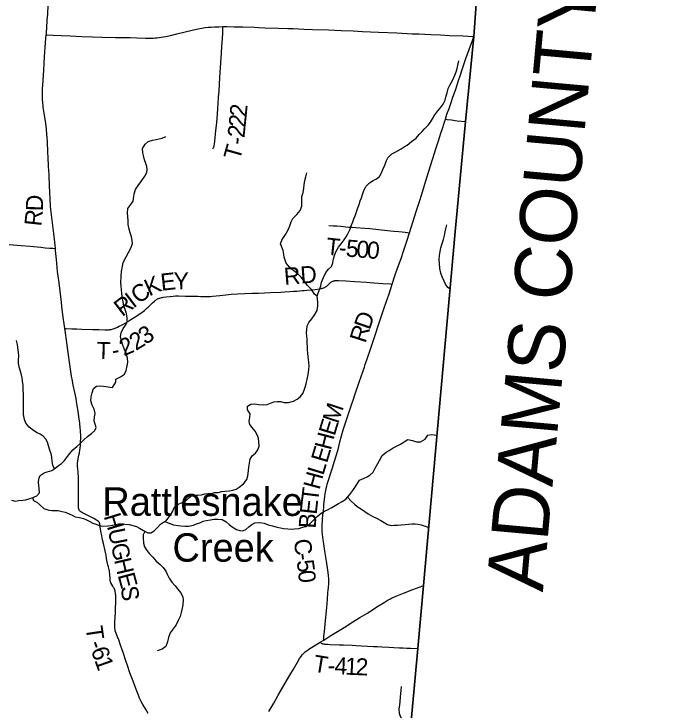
# Model space of a CAD drawing. Extents: x 1451455 to 1749751, y 218250 to 574981.
# Drawn here: x 1622321 to 1633736, y 302693 to 314948 of the extents above; entities that cross this region are included whole.
import ezdxf

# ---------------------------------------------------------------- set-up
doc = ezdxf.new("R2010")
doc.units = 0
for name, color, linetype in [('GM_X_Adjacent_County', 7, 'Continuous'), ('GM_X_Adjacent_County_Text', 7, 'Continuous'), ('GM_X_County', 7, 'Continuous'), ('GM_X_County_Road', 7, 'Continuous'), ('GM_X_County_Road_Text', 7, 'Continuous'), ('GM_X_Minor_River', 7, 'Continuous'), ('GM_X_Minor_River_Text', 7, 'Continuous'), ('GM_X_Township', 7, 'Continuous'), ('GM_X_Township_Road', 7, 'Continuous'), ('GM_X_Township_Road_Text', 7, 'Continuous')]:
    doc.layers.add(name, color=color, linetype=linetype)

msp = doc.modelspace()

# ---------------------------------------------------------------- linework, layer by layer
at = {"layer": 'GM_X_Adjacent_County'}
msp.add_lwpolyline([(1628937, 298348), (1629433, 303775), (1629536, 304887), (1630089, 311112), (1630271, 313053), (1630419, 314553), (1630488, 315536), (1630722, 318179), (1630769, 318617), (1630954, 320913), (1631260, 324446), (1631493, 327825), (1631870, 332224), (1631939, 332801), (1632333, 337652), (1632719, 342502), (1633085, 347092), (1633093, 347197), (1633154, 348076), (1633224, 348842), (1633265, 349678), (1633736, 355308)], dxfattribs=at)
at = {"layer": 'GM_X_County'}
msp.add_lwpolyline([(1628937, 298348), (1629433, 303775), (1629536, 304887), (1630089, 311112), (1630271, 313053), (1630419, 314553), (1630488, 315536), (1630722, 318179), (1630769, 318617), (1630954, 320913), (1631260, 324446), (1631493, 327825), (1631870, 332224), (1631939, 332801), (1632333, 337652), (1632719, 342502), (1633085, 347092), (1633093, 347197), (1633154, 348076), (1633224, 348842), (1633265, 349678), (1633736, 355308)], dxfattribs=at)
at = {"layer": 'GM_X_County_Road'}
for points in [[(1622888, 314578), (1623011, 314574), (1623150, 314568), (1623309, 314560), (1623517, 314553), (1623706, 314547), (1623876, 314542), (1624109, 314536), (1624270, 314533), (1624368, 314531), (1624483, 314528), (1624637, 314523), (1624685, 314522), (1624729, 314522), (1624778, 314523), (1624808, 314525), (1624841, 314528), (1624877, 314532), (1624912, 314538), (1624997, 314553), (1625077, 314569), (1625189, 314595), (1625316, 314627), (1625482, 314669), (1625565, 314687), (1625628, 314699), (1625687, 314707), (1625743, 314713), (1625795, 314716), (1625851, 314719), (1625890, 314722), (1625932, 314723), (1625999, 314724)], [(1625999, 314724), (1626069, 314724), (1626198, 314723), (1626355, 314719), (1626555, 314713), (1626627, 314710), (1626739, 314705), (1626975, 314698), (1627142, 314693), (1627240, 314690), (1627424, 314682), (1627581, 314676), (1627863, 314667), (1628083, 314659), (1628296, 314649), (1628460, 314641), (1628742, 314628), (1629066, 314613), (1629335, 314600), (1629453, 314595), (1629663, 314586), (1629833, 314578), (1629990, 314571), (1630233, 314562), (1630318, 314558), (1630419, 314553)], [(1623051, 310821), (1623047, 310875), (1623041, 310930), (1623021, 311084), (1623004, 311224), (1622992, 311319), (1622980, 311410), (1622969, 311504), (1622964, 311566), (1622957, 311700), (1622953, 311805), (1622948, 311926), (1622946, 311979), (1622943, 312048), (1622939, 312120), (1622932, 312264), (1622924, 312434), (1622920, 312504), (1622917, 312569), (1622914, 312645), (1622911, 312709), (1622908, 312765), (1622903, 312831), (1622895, 312919), (1622883, 313017), (1622872, 313095), (1622844, 313270), (1622838, 313305), (1622834, 313338), (1622829, 313383), (1622826, 313448), (1622825, 313509), (1622825, 313566), (1622826, 313635), (1622829, 313694), (1622845, 313956), (1622853, 314073), (1622862, 314198), (1622872, 314362), (1622883, 314515), (1622888, 314578)], [(1629919, 313096), (1629947, 313181), (1629985, 313285), (1630022, 313391), (1630053, 313481), (1630080, 313561), (1630101, 313624), (1630152, 313776), (1630179, 313860), (1630228, 314007), (1630282, 314162), (1630396, 314479), (1630402, 314500), (1630419, 314553)], [(1629289, 311095), (1629317, 311188), (1629412, 311485), (1629463, 311648), (1629503, 311773), (1629572, 311992), (1629693, 312383), (1629759, 312593), (1629803, 312734), (1629834, 312831), (1629868, 312934), (1629897, 313028), (1629919, 313096)], [(1628984, 310192), (1629031, 310336), (1629072, 310457), (1629146, 310661), (1629178, 310754), (1629243, 310947), (1629289, 311095)], [(1622237, 310892), (1622449, 310873), (1622609, 310858), (1622793, 310841), (1622871, 310833), (1622949, 310826), (1622980, 310823), (1623006, 310822), (1623051, 310821)], [(1627776, 303926), (1627781, 303991), (1627789, 304079), (1627800, 304206), (1627817, 304389), (1627829, 304497), (1627836, 304572), (1627842, 304637), (1627852, 304758), (1627860, 304849), (1627865, 304921), (1627866, 304950), (1627866, 304977), (1627865, 304997), (1627864, 305019), (1627862, 305044), (1627860, 305068), (1627849, 305155), (1627825, 305314), (1627799, 305488), (1627780, 305618), (1627769, 305692), (1627757, 305783), (1627751, 305842), (1627749, 305863), (1627748, 305885), (1627747, 305907), (1627748, 305931), (1627749, 305952), (1627750, 305974), (1627753, 306015), (1627757, 306055), (1627763, 306127), (1627771, 306205), (1627776, 306264), (1627781, 306310), (1627798, 306449), (1627805, 306505), (1627809, 306532), (1627815, 306559), (1627822, 306597), (1627830, 306633), (1627840, 306671), (1627876, 306793), (1627901, 306872), (1627923, 306940), (1627969, 307077), (1627992, 307149), (1628029, 307281), (1628063, 307415), (1628090, 307520), (1628120, 307624), (1628166, 307765), (1628214, 307911), (1628271, 308082), (1628301, 308169), (1628326, 308244), (1628409, 308482), (1628495, 308730), (1628509, 308774), (1628548, 308892), (1628594, 309029), (1628681, 309294), (1628741, 309475), (1628842, 309773), (1628928, 310021), (1628984, 310192)], [(1627776, 303926), (1627904, 304005), (1628135, 304148), (1628288, 304245), (1628414, 304322), (1628534, 304396), (1628742, 304527), (1628839, 304588), (1628909, 304631), (1628941, 304648), (1628961, 304658), (1628983, 304668), (1629022, 304685), (1629065, 304703), (1629180, 304749), (1629348, 304815), (1629474, 304863), (1629536, 304887)], [(1626809, 302667), (1626897, 302817), (1626977, 302956), (1627018, 303027), (1627080, 303135), (1627182, 303308), (1627242, 303413), (1627315, 303537), (1627353, 303599), (1627377, 303635), (1627399, 303664), (1627411, 303678), (1627423, 303691), (1627437, 303704), (1627452, 303718), (1627467, 303730), (1627484, 303742), (1627533, 303776), (1627591, 303812), (1627713, 303887)], [(1627713, 303887), (1627776, 303926)]]:
    msp.add_lwpolyline(points, dxfattribs=at)
at = {"layer": 'GM_X_Minor_River'}
for points in [[(1628037, 310840), (1628082, 310903), (1628135, 310969), (1628172, 311022), (1628202, 311074), (1628235, 311150), (1628262, 311216), (1628289, 311289), (1628309, 311341), (1628330, 311395), (1628355, 311465), (1628377, 311533), (1628400, 311595), (1628421, 311655), (1628440, 311712), (1628458, 311768), (1628483, 311838), (1628522, 311916), (1628585, 311973), (1628647, 312013), (1628708, 312046), (1628762, 312085), (1628793, 312151), (1628815, 312207), (1628852, 312285), (1628883, 312365), (1628906, 312416), (1628979, 312484), (1629045, 312523), (1629140, 312576), (1629196, 312607), (1629247, 312639), (1629325, 312704), (1629404, 312763), (1629459, 312825), (1629508, 312876), (1629552, 312928), (1629619, 312989), (1629655, 313041), (1629692, 313103), (1629735, 313172), (1629786, 313240), (1629828, 313292), (1629883, 313359), (1629914, 313429), (1629933, 313505), (1629948, 313559), (1629970, 313638), (1629995, 313696), (1630044, 313776), (1630087, 313868), (1630110, 313929), (1630127, 313987), (1630142, 314071), (1630154, 314123)], [(1624231, 310505), (1624245, 310575), (1624299, 310674), (1624341, 310748), (1624382, 310824), (1624407, 310905), (1624404, 310957), (1624393, 311026), (1624367, 311094), (1624350, 311158), (1624333, 311239), (1624330, 311311), (1624326, 311375), (1624319, 311439), (1624328, 311521), (1624377, 311593), (1624420, 311654), (1624435, 311732), (1624439, 311784), (1624460, 311856), (1624507, 311928), (1624576, 312015), (1624627, 312095), (1624662, 312158), (1624666, 312212), (1624659, 312265), (1624645, 312315), (1624620, 312379), (1624603, 312454), (1624591, 312504), (1624588, 312578), (1624631, 312656), (1624688, 312703), (1624760, 312728), (1624824, 312740), (1624876, 312749), (1624929, 312760), (1624995, 312788)], [(1627659, 309980), (1627612, 310013), (1627565, 310090), (1627487, 310175), (1627434, 310249), (1627379, 310316), (1627318, 310373), (1627250, 310428), (1627177, 310492), (1627117, 310559), (1627083, 310664), (1627077, 310716), (1627062, 310782), (1627039, 310841), (1627017, 310901), (1627038, 310963), (1627067, 311014), (1627103, 311068), (1627152, 311146), (1627181, 311218), (1627204, 311289), (1627232, 311345), (1627305, 311416), (1627362, 311486), (1627391, 311566), (1627394, 311630), (1627392, 311680), (1627391, 311736), (1627414, 311804), (1627429, 311882), (1627433, 311942), (1627442, 312018), (1627461, 312080), (1627482, 312150)], [(1630001, 310104), (1629965, 310131), (1629924, 310192), (1629896, 310244), (1629861, 310319), (1629840, 310387), (1629823, 310465), (1629816, 310554), (1629812, 310626), (1629815, 310696), (1629826, 310764), (1629839, 310832), (1629864, 310904), (1629884, 310977), (1629903, 311047), (1629916, 311111), (1629929, 311163), (1629945, 311237)], [(1624992, 306005), (1625013, 306040), (1625076, 306127), (1625119, 306197), (1625143, 306261), (1625214, 306320), (1625274, 306341), (1625349, 306379), (1625402, 306432), (1625454, 306468), (1625510, 306475), (1625560, 306474), (1625624, 306484), (1625681, 306501), (1625733, 306505), (1625797, 306508), (1625851, 306521), (1625921, 306523), (1625979, 306542), (1626033, 306549), (1626115, 306551), (1626176, 306562), (1626232, 306581), (1626290, 306619), (1626365, 306674), (1626422, 306755), (1626441, 306815), (1626452, 306903), (1626458, 306969), (1626467, 307041), (1626480, 307111), (1626515, 307167), (1626573, 307216), (1626618, 307272), (1626639, 307338), (1626636, 307414), (1626626, 307474), (1626609, 307528), (1626572, 307601), (1626518, 307670), (1626477, 307720), (1626466, 307774), (1626478, 307848), (1626479, 307906), (1626436, 307977), (1626433, 308045), (1626493, 308081), (1626565, 308082), (1626631, 308073), (1626715, 308068), (1626781, 308075), (1626839, 308095), (1626898, 308118), (1626956, 308128), (1627018, 308125), (1627082, 308108), (1627156, 308107), (1627244, 308130), (1627311, 308168), (1627363, 308205), (1627408, 308269), (1627433, 308325), (1627451, 308378), (1627468, 308438), (1627487, 308518), (1627497, 308574), (1627508, 308634), (1627515, 308688), (1627519, 308748), (1627516, 308818), (1627505, 308909), (1627496, 308977), (1627491, 309035), (1627489, 309093), (1627486, 309147), (1627485, 309223), (1627479, 309279), (1627476, 309330), (1627477, 309394), (1627487, 309458), (1627514, 309517), (1627565, 309579), (1627620, 309654), (1627659, 309726), (1627673, 309808), (1627674, 309876), (1627665, 309926), (1627659, 309980), (1627686, 310050), (1627707, 310108), (1627725, 310162), (1627740, 310224), (1627773, 310306), (1627816, 310399), (1627863, 310457), (1627916, 310504), (1627940, 310568), (1627951, 310636), (1627968, 310698), (1627990, 310762), (1628037, 310840)], [(1622281, 306386), (1622340, 306373), (1622407, 306381), (1622477, 306386), (1622527, 306393), (1622587, 306413), (1622655, 306438), (1622722, 306465), (1622770, 306519), (1622767, 306593), (1622762, 306647), (1622754, 306701), (1622761, 306763), (1622786, 306821), (1622856, 306868), (1622909, 306888), (1622989, 306913), (1623039, 306943), (1623108, 306996), (1623159, 307033), (1623209, 307087), (1623262, 307156), (1623305, 307208), (1623359, 307274), (1623428, 307333), (1623495, 307392), (1623554, 307448), (1623616, 307507), (1623685, 307560), (1623746, 307614), (1623772, 307666), (1623753, 307726), (1623735, 307778), (1623742, 307856), (1623753, 307912), (1623736, 307988), (1623699, 308061), (1623677, 308137), (1623684, 308209), (1623699, 308277), (1623722, 308355), (1623776, 308397), (1623835, 308400), (1623901, 308397), (1623982, 308384), (1624058, 308371), (1624113, 308463), (1624118, 308517), (1624197, 308562), (1624267, 308608), (1624298, 308673), (1624317, 308755), (1624328, 308819), (1624322, 308887), (1624297, 308974), (1624262, 309054), (1624235, 309135), (1624212, 309215), (1624197, 309267), (1624209, 309337), (1624244, 309411), (1624289, 309477), (1624314, 309530), (1624316, 309596), (1624305, 309677), (1624280, 309745), (1624259, 309803), (1624243, 309878), (1624232, 309938), (1624221, 310026), (1624214, 310098), (1624209, 310156), (1624205, 310219), (1624210, 310323), (1624217, 310413), (1624231, 310505)], [(1623036, 306940), (1623004, 307005), (1622995, 307077), (1622986, 307143), (1622976, 307202), (1622955, 307268), (1622932, 307346), (1622915, 307409), (1622885, 307465), (1622836, 307516), (1622784, 307548), (1622728, 307575), (1622667, 307616), (1622589, 307676), (1622530, 307743), (1622505, 307810), (1622492, 307894), (1622488, 307952), (1622487, 308006), (1622488, 308062), (1622490, 308112), (1622491, 308178), (1622488, 308246), (1622483, 308339), (1622481, 308405), (1622474, 308485), (1622465, 308543), (1622452, 308597), (1622430, 308676), (1622415, 308732), (1622402, 308804), (1622403, 308862), (1622405, 308924), (1622404, 308996), (1622391, 309073), (1622382, 309127), (1622364, 309197)], [(1628805, 307172), (1628877, 307231), (1628928, 307265), (1628998, 307308), (1629059, 307339), (1629127, 307373), (1629196, 307416), (1629256, 307455), (1629342, 307438), (1629410, 307414), (1629480, 307417), (1629563, 307462), (1629613, 307530), (1629674, 307543), (1629766, 307531)], [(1622646, 306434), (1622667, 306384), (1622725, 306355), (1622776, 306309), (1622849, 306240), (1622935, 306213), (1622991, 306206), (1623047, 306207), (1623101, 306205), (1623169, 306190), (1623221, 306176), (1623295, 306149), (1623346, 306124), (1623400, 306097), (1623476, 306085), (1623546, 306068), (1623598, 306043), (1623657, 306013), (1623713, 305986), (1623769, 305963), (1623833, 305937), (1623889, 305930), (1623983, 305939), (1624059, 305950), (1624113, 305960), (1624163, 305969), (1624215, 305972), (1624277, 305968), (1624351, 305959), (1624417, 305944), (1624479, 305923), (1624535, 305897), (1624600, 305854), (1624678, 305811), (1624732, 305815), (1624790, 305850), (1624847, 305909), (1624904, 305967), (1624974, 306010), (1625040, 305989), (1625132, 305956), (1625210, 305940), (1625262, 305935), (1625334, 305928), (1625394, 305932), (1625482, 305947), (1625538, 305974), (1625597, 305991), (1625653, 306017), (1625707, 306028), (1625781, 306045), (1625840, 306051), (1625912, 306056), (1625986, 306047), (1626059, 306006), (1626111, 305960), (1626166, 305921), (1626242, 305874), (1626302, 305852), (1626354, 305847), (1626406, 305870), (1626459, 305920), (1626513, 305959), (1626563, 305989), (1626654, 305998), (1626726, 305983), (1626799, 305956), (1626875, 305935), (1626933, 305921), (1627015, 305904), (1627071, 305889), (1627147, 305882), (1627205, 305878), (1627265, 305881), (1627341, 305892), (1627411, 305912), (1627461, 305927), (1627532, 305970), (1627605, 306042), (1627664, 306101), (1627734, 306158), (1627791, 306192), (1627857, 306225), (1627922, 306262), (1627980, 306296), (1628036, 306327), (1628103, 306363), (1628165, 306408), (1628234, 306487), (1628289, 306561), (1628326, 306612), (1628359, 306666), (1628407, 306740), (1628488, 306775), (1628540, 306798), (1628591, 306828), (1628645, 306881), (1628684, 306949), (1628729, 307031), (1628760, 307084), (1628805, 307172)], [(1628197, 306444), (1628261, 306371), (1628317, 306320), (1628368, 306278), (1628442, 306227), (1628499, 306188), (1628561, 306145), (1628644, 306098), (1628708, 306070), (1628782, 306031), (1628839, 305998), (1628901, 305959), (1628965, 305943), (1629017, 305946), (1629077, 305949), (1629141, 305955), (1629211, 305960), (1629269, 305963), (1629333, 305969), (1629387, 305970), (1629439, 305965), (1629493, 305955), (1629619, 305915)], [(1624629, 305838), (1624599, 305778), (1624597, 305724), (1624604, 305630), (1624623, 305569), (1624660, 305503), (1624708, 305444), (1624765, 305382), (1624826, 305317), (1624894, 305254), (1624951, 305201), (1624997, 305139), (1625022, 305084), (1625055, 305014), (1625100, 304947), (1625158, 304881), (1625199, 304830), (1625256, 304760), (1625294, 304685), (1625301, 304631), (1625296, 304543), (1625285, 304489), (1625269, 304409), (1625246, 304343), (1625211, 304267), (1625178, 304196), (1625123, 304122), (1625074, 304055), (1625041, 303971), (1625023, 303897), (1624994, 303811), (1624933, 303768), (1624845, 303737)], [(1629299, 302409), (1629247, 302433), (1629168, 302506), (1629127, 302577), (1629109, 302633), (1629108, 302713), (1629119, 302777), (1629124, 302843), (1629131, 302919), (1629135, 302985), (1629138, 303039), (1629147, 303109)]]:
    msp.add_lwpolyline(points, dxfattribs=at)
at = {"layer": 'GM_X_Township'}
msp.add_lwpolyline([(1614660, 311985), (1615038, 312176), (1620528, 319060), (1620626, 319183), (1620666, 319169), (1621267, 318945), (1621491, 318927), (1624271, 318701), (1630722, 318179), (1630488, 315536), (1630419, 314553), (1630271, 313053), (1630089, 311112), (1629536, 304887), (1629433, 303775), (1628937, 298348)], dxfattribs=at)
at = {"layer": 'GM_X_Township_Road'}
for points in [[(1622929, 315227), (1622925, 315168), (1622921, 315102), (1622910, 314942), (1622903, 314840), (1622894, 314705), (1622890, 314626), (1622888, 314578)], [(1625822, 312571), (1625835, 312597), (1625839, 312604), (1625843, 312614), (1625845, 312623), (1625847, 312633), (1625851, 312654), (1625857, 312710), (1625878, 312896), (1625893, 313029), (1625901, 313121), (1625904, 313170), (1625913, 313297), (1625917, 313363), (1625926, 313480), (1625933, 313591), (1625947, 313830), (1625952, 313919), (1625976, 314256), (1625984, 314380), (1625993, 314507), (1625999, 314620), (1626000, 314656), (1626000, 314688), (1625999, 314724)], [(1629919, 313096), (1629952, 313090), (1630025, 313081), (1630126, 313069), (1630271, 313053)], [(1627869, 311226), (1627943, 311220), (1628005, 311215), (1628077, 311209), (1628165, 311201), (1628217, 311197), (1628279, 311192), (1628341, 311187), (1628498, 311176), (1628589, 311168), (1628850, 311141), (1628952, 311131), (1629010, 311125), (1629102, 311117), (1629210, 311105), (1629255, 311099), (1629289, 311095)], [(1623217, 309412), (1623184, 309651), (1623172, 309752), (1623151, 309922), (1623116, 310215), (1623091, 310413), (1623070, 310625), (1623060, 310731), (1623054, 310785), (1623051, 310821)], [(1623217, 309412), (1623242, 309411), (1623341, 309407), (1623426, 309404), (1623515, 309401), (1623708, 309394), (1623819, 309390), (1623921, 309387), (1623977, 309388), (1623991, 309389), (1624006, 309390), (1624021, 309392), (1624035, 309395), (1624050, 309400), (1624066, 309405), (1624103, 309418), (1624145, 309436), (1624175, 309449), (1624227, 309476), (1624290, 309512), (1624343, 309544), (1624382, 309569), (1624437, 309604), (1624519, 309658), (1624578, 309698), (1624620, 309730), (1624658, 309761), (1624687, 309787), (1624762, 309861), (1624796, 309892), (1624807, 309901), (1624819, 309910), (1624830, 309918), (1624841, 309924), (1624852, 309930), (1624865, 309936), (1624877, 309942), (1624892, 309947), (1624906, 309951), (1624923, 309956), (1624937, 309959), (1624952, 309962), (1625004, 309969), (1625073, 309976), (1625128, 309981), (1625167, 309983), (1625220, 309984), (1625345, 309982), (1625436, 309980), (1625558, 309977), (1625613, 309976), (1625666, 309975), (1625744, 309975), (1625777, 309975), (1625817, 309978), (1625947, 309993), (1626054, 310005), (1626146, 310012), (1626257, 310018), (1626519, 310030), (1626631, 310034), (1626837, 310044), (1627017, 310052), (1627086, 310056), (1627181, 310062), (1627246, 310066), (1627301, 310070), (1627399, 310078), (1627435, 310080), (1627481, 310084), (1627562, 310091), (1627624, 310098), (1627705, 310110), (1627738, 310116), (1627751, 310119), (1627763, 310122), (1627775, 310125), (1627788, 310130), (1627799, 310135), (1627811, 310142), (1627819, 310148), (1627829, 310156), (1627848, 310174), (1627883, 310209), (1627892, 310217), (1627903, 310225), (1627912, 310231), (1627923, 310237), (1627935, 310242), (1627943, 310245), (1627953, 310248), (1627964, 310251), (1627975, 310253), (1627988, 310255), (1628002, 310256), (1628019, 310256), (1628035, 310255), (1628169, 310249), (1628323, 310239), (1628532, 310224), (1628660, 310214), (1628820, 310204), (1628950, 310195), (1628984, 310192)], [(1624111, 304742), (1624109, 304753), (1624106, 304772), (1624102, 304789), (1624097, 304805), (1624090, 304823), (1624084, 304838), (1624076, 304852), (1624063, 304875), (1624045, 304903), (1624028, 304935), (1624023, 304948), (1624018, 304962), (1624015, 304974), (1624014, 304988), (1624013, 305006), (1624013, 305034), (1624012, 305063), (1624011, 305080), (1624010, 305096), (1624006, 305119), (1624002, 305141), (1623996, 305167), (1623984, 305214), (1623975, 305252), (1623970, 305274), (1623953, 305364), (1623943, 305419), (1623926, 305499), (1623898, 305623), (1623883, 305690), (1623867, 305763), (1623851, 305840), (1623843, 305882), (1623839, 305911), (1623837, 305944), (1623836, 305958), (1623834, 305970), (1623833, 305979), (1623830, 305986), (1623826, 305995), (1623822, 306001), (1623819, 306006), (1623813, 306012), (1623808, 306017), (1623801, 306022), (1623794, 306027), (1623777, 306038), (1623731, 306063), (1623600, 306131), (1623526, 306167), (1623512, 306175), (1623501, 306181), (1623493, 306187), (1623485, 306194), (1623477, 306203), (1623472, 306212), (1623467, 306221), (1623463, 306233), (1623460, 306241), (1623459, 306251), (1623457, 306263), (1623457, 306275), (1623457, 306325), (1623458, 306439), (1623459, 306524), (1623460, 306629), (1623460, 306704), (1623459, 306781), (1623457, 306811), (1623454, 306853), (1623452, 306876), (1623450, 306898), (1623447, 306921), (1623444, 306947), (1623442, 306976), (1623441, 307012), (1623442, 307048), (1623445, 307077), (1623452, 307118), (1623466, 307182), (1623474, 307220), (1623483, 307271), (1623487, 307304), (1623492, 307356), (1623496, 307421), (1623497, 307471), (1623497, 307500), (1623497, 307536), (1623495, 307585), (1623492, 307620), (1623489, 307656), (1623480, 307744), (1623465, 307854), (1623451, 307957), (1623437, 308048), (1623429, 308093), (1623425, 308122), (1623415, 308177), (1623393, 308286), (1623367, 308412), (1623351, 308489), (1623337, 308573), (1623312, 308738), (1623271, 309031), (1623246, 309206), (1623227, 309336), (1623217, 309412)], [(1624683, 302630), (1624636, 302713), (1624590, 302792), (1624568, 302832), (1624550, 302867), (1624535, 302900), (1624513, 302954), (1624485, 303028), (1624461, 303092), (1624451, 303117), (1624418, 303202), (1624397, 303258), (1624380, 303304), (1624358, 303369), (1624327, 303462), (1624288, 303577), (1624245, 303704), (1624221, 303773), (1624205, 303819), (1624160, 303945), (1624152, 303967), (1624126, 304027), (1624113, 304061), (1624106, 304086), (1624102, 304109), (1624099, 304138), (1624098, 304181), (1624098, 304237), (1624104, 304335), (1624107, 304400), (1624112, 304515), (1624113, 304557), (1624114, 304623), (1624115, 304682), (1624114, 304699), (1624113, 304718), (1624112, 304735), (1624111, 304742)], [(1627713, 303887), (1627726, 303876), (1627733, 303871), (1627741, 303867), (1627748, 303864), (1627756, 303862), (1627763, 303860), (1627771, 303858), (1627781, 303857), (1627793, 303856), (1627843, 303853), (1627888, 303850), (1628046, 303844), (1628127, 303840), (1628278, 303833), (1628350, 303830), (1628445, 303825), (1628546, 303820), (1628651, 303814), (1628723, 303811), (1628799, 303809), (1628923, 303802), (1629011, 303797), (1629113, 303790), (1629175, 303788), (1629240, 303785), (1629303, 303782), (1629433, 303775)]]:
    msp.add_lwpolyline(points, dxfattribs=at)

# ---------------------------------------------------------------- texts
at = {"layer": 'GM_X_Adjacent_County_Text'}
msp.add_text('ADAMS COUNTY', height=1000, rotation=84.8148, dxfattribs=at).set_placement((1631636, 304763))
at = {"layer": 'GM_X_County_Road_Text'}
for s, rotation, p in [('D', 88.3902, (1622830, 311472)), ('R', 83.6958, (1622801, 311201)), ('D', 70.8099, (1628586, 309373)), ('R', 72.1248, (1628511, 309140)), ('M', 71.983, (1628033, 307721)), ('E', 73.035, (1627968, 307507)), ('H', 75.4675, (1627902, 307255)), ('E', 73.2044, (1627834, 307028)), ('L', 73.0038, (1627768, 306812)), ('H', 74.9883, (1627701, 306560)), ('T', 83.0576, (1627676, 306348)), ('E', 83.7391, (1627651, 306126)), ('B', 86.0276, (1627634, 305883)), ('C', 278.2402, (1627246, 305687)), ('-', 278.2008, (1627282, 305443)), ('5', 278.009, (1627299, 305321)), ('0', 275.4359, (1627324, 305142))]:
    msp.add_text(s, height=300, rotation=rotation, dxfattribs=at).set_placement(p)
at = {"layer": 'GM_X_Minor_River_Text'}
for s, height, rotation, p in [('Rattlesnake', 499.98, 359.947, (1623878, 306114)), ('Creek', 500, 359.9471, (1625113, 305306))]:
    msp.add_text(s, height=height, rotation=rotation, dxfattribs=at).set_placement(p)
at = {"layer": 'GM_X_Township_Road_Text'}
for s, rotation, p in [('2', 84.2741, (1626416, 313126)), ('2', 84.2573, (1626398, 312942)), ('2', 84.1615, (1626379, 312758)), ('-', 85.4466, (1626369, 312637)), ('T', 74.3436, (1626297, 312358)), ('T', 353.8898, (1627805, 310714)), ('5', 355.3354, (1628159, 310679)), ('0', 355.4528, (1628344, 310664)), ('0', 355.4752, (1628529, 310649)), ('-', 355.0768, (1628035, 310690)), ('RD', 4.3216, (1627087, 310178)), ('K', 24.3163, (1624703, 309972)), ('E', 6.2351, (1624919, 310074)), ('Y', 0.2605, (1625134, 310098)), ('C', 37.1236, (1624521, 309832)), ('R', 37.3312, (1624228, 309608)), ('I', 37.3315, (1624424, 309758)), ('3', 33.7812, (1624638, 309117)), ('2', 31.2416, (1624468, 309013)), ('2', 23.1494, (1624257, 308919)), ('T', 358.3113, (1623773, 308876)), ('-', 10.8606, (1624069, 308876)), ('H', 287.0052, (1623899, 306107)), ('U', 281.5453, (1623975, 305862)), ('G', 281.6057, (1624028, 305603)), ('H', 283.2032, (1624083, 305336)), ('E', 284.9633, (1624146, 305069)), ('S', 277.6248, (1624201, 304862)), ('T', 278.3089, (1623581, 304153)), ('-', 290.3575, (1623631, 303864)), ('6', 289.35, (1623673, 303750)), ('1', 289.5734, (1623735, 303574)), ('T', 350.7025, (1627579, 303372)), ('4', 357.246, (1627963, 303327)), ('1', 357.3056, (1628148, 303318)), ('2', 357.3289, (1628333, 303310)), ('-', 357.7964, (1627841, 303332))]:
    msp.add_text(s, height=300, rotation=rotation, dxfattribs=at).set_placement(p)

doc.saveas('drawing.dxf')
